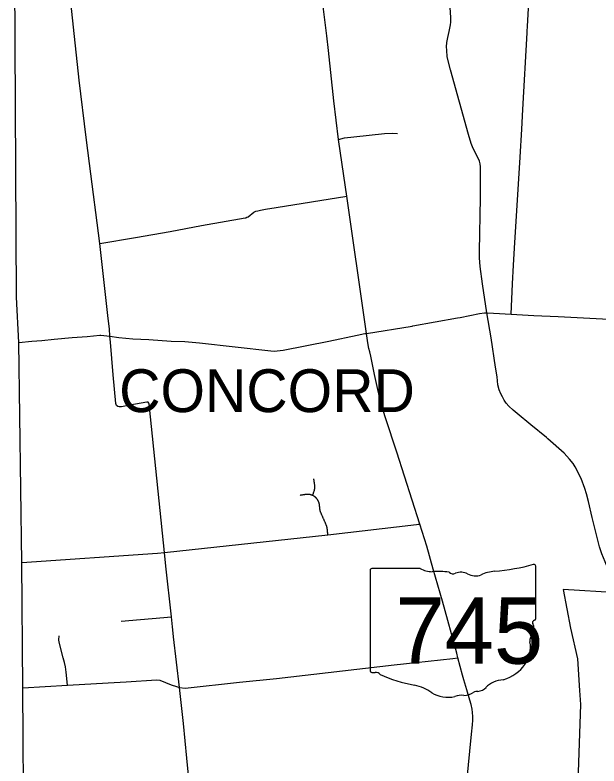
# Model space of a CAD drawing. Extents: x 1729596 to 1925846, y 659247 to 911751.
# Drawn here: x 1780895 to 1793175, y 791458 to 807237 of the extents above; entities that cross this region are included whole.
import ezdxf

# ---------------------------------------------------------------- set-up
doc = ezdxf.new("R2010")
doc.units = 0
for name, color, linetype in [('GM_X_County', 7, 'Continuous'), ('GM_X_County_Road', 7, 'Continuous'), ('GM_X_State_Route', 7, 'Continuous'), ('GM_X_State_Shield', 7, 'Continuous'), ('GM_X_Township', 7, 'Continuous'), ('GM_X_Township_Road', 7, 'Continuous'), ('GM_X_Township_Text', 7, 'Continuous')]:
    doc.layers.add(name, color=color, linetype=linetype)

msp = doc.modelspace()

# ---------------------------------------------------------------- linework, layer by layer
at = {"layer": 'GM_X_County'}
msp.add_lwpolyline([(1781083, 789921), (1781062, 793102), (1781040, 795733), (1780979, 800357), (1780927, 801312), (1780895, 808002)], dxfattribs=at)
at = {"layer": 'GM_X_County_Road'}
for points in [[(1782890, 800490), (1782881, 800644), (1782856, 800863), (1782676, 802437), (1782464, 804119), (1782395, 804661), (1782246, 805871), (1782006, 808105), (1781669, 811078), (1781659, 811109), (1781650, 811131), (1781636, 811151)], [(1791328, 800949), (1791359, 801588), (1791381, 801980), (1791400, 802336), (1791517, 804248), (1791555, 804839), (1791576, 805255), (1791663, 806861), (1791666, 806898), (1791673, 806996), (1791713, 807764)], [(1790259, 800884), (1790662, 800965), (1790767, 800980), (1790816, 800981)], [(1790816, 800981), (1790957, 800973), (1791328, 800949), (1791805, 800926), (1792317, 800900), (1794586, 800781), (1795455, 800738), (1796520, 800687)], [(1789248, 800701), (1789260, 800704), (1790202, 800872), (1790259, 800884)], [(1788284, 800545), (1789248, 800701)], [(1780979, 800357), (1781251, 800385), (1781456, 800401), (1781721, 800423), (1782095, 800460), (1782415, 800484), (1782676, 800509), (1782703, 800508), (1782890, 800490), (1783080, 800464), (1783370, 800430), (1783710, 800417), (1784177, 800386), (1784465, 800376), (1784774, 800347), (1786277, 800180), (1786348, 800171), (1786537, 800193), (1787491, 800386), (1788093, 800511), (1788252, 800542), (1788284, 800545)], [(1784231, 794169), (1784213, 794320), (1784208, 794381), (1784184, 794592), (1784065, 795658), (1784036, 795945), (1783745, 798796), (1783719, 799058), (1783710, 799082), (1783697, 799100), (1783664, 799103), (1783307, 799040), (1783135, 799003), (1783086, 799003), (1783057, 799012), (1783029, 799032), (1783012, 799071), (1782957, 799680), (1782900, 800360), (1782890, 800490)], [(1784354, 793107), (1784231, 794169)]]:
    msp.add_lwpolyline(points, dxfattribs=at)
at = {"layer": 'GM_X_State_Route'}
for points in [[(1790208, 793730), (1790185, 793831), (1789883, 794924), (1789691, 795593), (1789552, 796074), (1789406, 796539), (1788925, 798054), (1788685, 798770), (1788593, 799061), (1788574, 799137), (1788559, 799211), (1788513, 799432), (1788454, 799683), (1788376, 800070), (1788357, 800160), (1788339, 800233), (1788316, 800352), (1788284, 800545), (1788263, 800693), (1787872, 803431), (1787846, 803622), (1787700, 804624), (1787601, 805437), (1787484, 806491), (1787451, 806800), (1787357, 807594)], [(1790677, 804093), (1790675, 804108), (1790660, 804164), (1790640, 804215), (1790609, 804281), (1790568, 804355), (1790526, 804429), (1790485, 804541), (1790432, 804726), (1790051, 806083), (1789985, 806362), (1789973, 806499), (1789971, 806567), (1789977, 806663), (1789996, 806768), (1790026, 806892), (1790053, 807030), (1790058, 807087), (1790058, 807184), (1790033, 807604)], [(1790684, 803416), (1790687, 803933), (1790683, 804011), (1790681, 804061), (1790677, 804093)], [(1790816, 800981), (1790725, 801587), (1790674, 801951), (1790662, 802137), (1790662, 802272), (1790684, 803396), (1790684, 803416)], [(1792099, 798333), (1792069, 798359), (1791739, 798628), (1791453, 798865), (1791371, 798933), (1791282, 799017), (1791224, 799083), (1791180, 799145), (1791143, 799214), (1791110, 799281), (1791078, 799363), (1791051, 799466), (1791032, 799632), (1791000, 799840), (1790910, 800451), (1790816, 800981)], [(1793626, 794462), (1793626, 794462), (1793641, 794594), (1793644, 794648), (1793641, 794771), (1793623, 794897), (1793613, 794945), (1793580, 795059), (1793566, 795094), (1793498, 795270), (1793303, 795745), (1793237, 795913), (1793188, 796062), (1793091, 796453), (1793034, 796681), (1792957, 797013), (1792916, 797174), (1792881, 797288), (1792802, 797495), (1792672, 797742), (1792629, 797811), (1792556, 797903), (1792444, 798033), (1792099, 798333)], [(1790307, 793367), (1790208, 793730)], [(1790432, 790335), (1790390, 790706), (1790390, 790920), (1790399, 791128), (1790496, 792123), (1790514, 792320), (1790520, 792424), (1790521, 792501), (1790516, 792584), (1790507, 792652), (1790487, 792748), (1790462, 792838), (1790399, 793056), (1790334, 793268), (1790307, 793367)]]:
    msp.add_lwpolyline(points, dxfattribs=at)
at = {"layer": 'GM_X_State_Shield'}
for p, q in [((1789418, 795607), (1788399, 795607)), ((1789418, 795607), (1788399, 795607)), ((1791845, 794554), (1791845, 795660)), ((1791845, 794554), (1791845, 795660)), ((1788365, 795571), (1788365, 793458)), ((1788365, 795571), (1788365, 793458)), ((1791845, 794555), (1791845, 794554)), ((1791845, 794555), (1791845, 794554))]:
    msp.add_line(p, q, dxfattribs=at)
for centre, major_axis, start_param, end_param in [((1788404, 795576), (40.3, 0), 1.712693, 3.28349), ((1788404, 795576), (40.3, 0), 1.712693, 3.28349), ((1789661, 795853), (391, 0), 4.042523, 4.731795), ((1789661, 795853), (391, 0), 4.042523, 4.731795), ((1790605, 798489), (3691, 0), 4.814394, 5.042369), ((1790605, 798489), (3691, 0), 4.814394, 5.042369), ((1791806, 795664), (38.7, 0), 6.141152, 7.989035), ((1791806, 795664), (38.7, 0), 6.141152, 7.989035), ((1789791, 794421), (1404, 0), 1.404758, 1.657858), ((1789791, 794421), (1404, 0), 1.404758, 1.657858), ((1790109, 795587), (113, 0), 3.836095, 5.185415), ((1790109, 795587), (113, 0), 3.836095, 5.185415), ((1790275, 795342), (235, 0), 0.950623, 2.079405), ((1790275, 795342), (235, 0), 0.950623, 2.079405), ((1790578, 795677), (282, 0), 4.081561, 5.145723), ((1790578, 795677), (282, 0), 4.081561, 5.145723), ((1791076, 794962), (743, 0), 1.699011, 2.107814), ((1791076, 794962), (743, 0), 1.699011, 2.107814), ((1791836, 794473), (60, 0), 1.883978, 3.671073), ((1791836, 794473), (60, 0), 1.883978, 3.671073), ((1791804, 794550), (41.5, 0), 5.05454, 6.418171), ((1791804, 794550), (41.5, 0), 5.05454, 6.418171), ((1791455, 794333), (360, 0), 5.934695, 6.695948), ((1791455, 794333), (360, 0), 5.934695, 6.695948), ((1791984, 794092), (262, 0), 2.387724, 3.262537), ((1791984, 794092), (262, 0), 2.387724, 3.262537), ((1790812, 793951), (923, 0), 5.101752, 6.440018), ((1790812, 793951), (923, 0), 5.101752, 6.440018), ((1788405, 793453), (40.7, 0), 3.00124, 4.508301), ((1788405, 793453), (40.7, 0), 3.00124, 4.508301), ((1788411, 793669), (310, 0), 4.665946, 4.897461), ((1788411, 793669), (310, 0), 4.665946, 4.897461), ((1788475, 793336), (112, 0), 0.519207, 1.627899), ((1788475, 793336), (112, 0), 0.519207, 1.627899), ((1789888, 795235), (2665, 0), 4.195997, 4.488961), ((1789888, 795235), (2665, 0), 4.195997, 4.488961), ((1791201, 792864), (506, 0), 1.647645, 2.488434), ((1791201, 792864), (506, 0), 1.647645, 2.488434), ((1789093, 792508), (834, 0), 0.823519, 1.323587), ((1789093, 792508), (834, 0), 0.823519, 1.323587), ((1790561, 793253), (298, 0), 4.937069, 5.64225), ((1790561, 793253), (298, 0), 4.937069, 5.64225), ((1789995, 793325), (529, 0), 4.026481, 4.996735), ((1789995, 793325), (529, 0), 4.026481, 4.996735), ((1790301, 792595), (435, 0), 1.495662, 1.94098), ((1790301, 792595), (435, 0), 1.495662, 1.94098), ((1790339, 793167), (282, 0), 4.691044, 5.507374), ((1790339, 793167), (282, 0), 4.691044, 5.507374), ((1790595, 792962), (79.4, 0), 1.147584, 2.315152), ((1790595, 792962), (79.4, 0), 1.147584, 2.315152)]:
    msp.add_ellipse(centre, major_axis=major_axis, ratio=0.8, start_param=start_param, end_param=end_param, dxfattribs=at)
at = {"layer": 'GM_X_Township'}
msp.add_lwpolyline([(1793566, 795094), (1792419, 795165), (1792576, 794356), (1792720, 793710), (1792764, 793045), (1792783, 792753), (1792702, 790313), (1792702, 789519), (1792745, 788755), (1792845, 788222), (1793028, 787628), (1793570, 786064)], dxfattribs=at)
at = {"layer": 'GM_X_Township_Road'}
for points in [[(1787700, 804624), (1787823, 804655), (1788019, 804676), (1788666, 804747), (1788824, 804753), (1788939, 804749)], [(1782676, 802437), (1783430, 802559), (1784155, 802688), (1784818, 802812), (1785735, 802974), (1785747, 802978), (1785772, 802987), (1785797, 802999), (1785838, 803032), (1785874, 803062), (1785916, 803092), (1785959, 803113), (1786003, 803125), (1786060, 803139), (1786163, 803159), (1786385, 803195), (1787872, 803431)], [(1787154, 797141), (1787157, 797150), (1787160, 797159), (1787163, 797168), (1787166, 797177), (1787169, 797185), (1787172, 797194), (1787175, 797203), (1787178, 797212), (1787181, 797221), (1787184, 797230), (1787187, 797238), (1787189, 797242), (1787190, 797247), (1787191, 797251), (1787192, 797255), (1787194, 797259), (1787195, 797263), (1787196, 797267), (1787196, 797272), (1787197, 797276), (1787198, 797280), (1787199, 797284), (1787199, 797288), (1787200, 797293), (1787200, 797297), (1787200, 797301), (1787201, 797306), (1787201, 797310), (1787201, 797314), (1787201, 797319), (1787201, 797323), (1787201, 797327), (1787201, 797331), (1787201, 797336), (1787200, 797340), (1787200, 797344), (1787199, 797349), (1787199, 797353), (1787198, 797357), (1787197, 797366), (1787196, 797376), (1787194, 797385), (1787193, 797395), (1787191, 797404), (1787190, 797413), (1787188, 797423), (1787187, 797432), (1787186, 797442), (1787184, 797451), (1787183, 797460), (1787181, 797470), (1787180, 797479), (1787178, 797489)], [(1787475, 796318), (1787474, 796328), (1787473, 796338), (1787472, 796348), (1787471, 796358), (1787469, 796367), (1787468, 796377), (1787467, 796387), (1787466, 796397), (1787465, 796406), (1787464, 796416), (1787463, 796426), (1787462, 796436), (1787461, 796445), (1787460, 796450), (1787460, 796454), (1787459, 796458), (1787458, 796462), (1787458, 796466), (1787457, 796470), (1787456, 796474), (1787455, 796479), (1787454, 796483), (1787453, 796487), (1787452, 796491), (1787450, 796495), (1787449, 796499), (1787448, 796503), (1787446, 796507), (1787445, 796511), (1787443, 796514), (1787441, 796518), (1787437, 796527), (1787433, 796536), (1787429, 796545), (1787425, 796555), (1787421, 796564), (1787418, 796573), (1787414, 796582), (1787410, 796591), (1787406, 796600), (1787402, 796609), (1787398, 796618), (1787394, 796627), (1787390, 796636), (1787386, 796645), (1787382, 796654), (1787378, 796663), (1787374, 796672), (1787370, 796681), (1787366, 796690), (1787362, 796699), (1787358, 796708), (1787354, 796717), (1787350, 796726), (1787346, 796735), (1787342, 796744), (1787338, 796753), (1787334, 796762), (1787330, 796772), (1787326, 796781), (1787325, 796784), (1787323, 796788), (1787322, 796792), (1787320, 796796), (1787319, 796800), (1787317, 796804), (1787316, 796808), (1787315, 796812), (1787314, 796816), (1787313, 796820), (1787312, 796824), (1787311, 796828), (1787310, 796832), (1787309, 796836), (1787309, 796840), (1787308, 796844), (1787307, 796848), (1787307, 796852), (1787306, 796857), (1787306, 796866), (1787305, 796875), (1787304, 796884), (1787303, 796893), (1787302, 796902), (1787301, 796911), (1787300, 796920), (1787299, 796930), (1787298, 796939), (1787298, 796943), (1787297, 796947), (1787297, 796952), (1787296, 796956), (1787295, 796960), (1787294, 796964), (1787294, 796969), (1787293, 796973), (1787292, 796977), (1787290, 796981), (1787289, 796986), (1787288, 796990), (1787287, 796994), (1787285, 796998), (1787284, 797002), (1787282, 797006), (1787280, 797010), (1787279, 797014), (1787277, 797018), (1787275, 797022), (1787273, 797026), (1787271, 797030), (1787269, 797034), (1787267, 797037), (1787266, 797039), (1787265, 797041), (1787263, 797045), (1787260, 797049), (1787258, 797052), (1787256, 797056), (1787253, 797059), (1787251, 797063), (1787248, 797066), (1787245, 797070), (1787243, 797073), (1787240, 797076), (1787237, 797080), (1787234, 797083), (1787231, 797086), (1787228, 797089), (1787225, 797092), (1787222, 797095), (1787219, 797098), (1787216, 797101), (1787212, 797104), (1787209, 797107), (1787206, 797110), (1787202, 797112), (1787199, 797115), (1787195, 797117), (1787192, 797120), (1787188, 797122), (1787184, 797125), (1787181, 797127), (1787177, 797129), (1787173, 797132), (1787169, 797134), (1787166, 797136), (1787162, 797138), (1787158, 797140), (1787154, 797141), (1787150, 797143), (1787146, 797145), (1787142, 797147), (1787138, 797148), (1787134, 797150), (1787130, 797151), (1787126, 797152), (1787122, 797154), (1787118, 797155), (1787114, 797156), (1787109, 797157), (1787105, 797158), (1787101, 797159), (1787097, 797160), (1787093, 797161), (1787088, 797161), (1787084, 797162), (1787080, 797162), (1787076, 797163), (1787071, 797163), (1787067, 797164), (1787063, 797164), (1787059, 797164), (1787054, 797164), (1787050, 797164), (1787046, 797164), (1787041, 797164), (1787037, 797164), (1787033, 797164), (1787029, 797163), (1787024, 797163), (1787020, 797163), (1787016, 797162), (1787012, 797161), (1787002, 797160), (1786993, 797159), (1786984, 797157), (1786974, 797156), (1786965, 797154), (1786956, 797153), (1786946, 797152), (1786937, 797150), (1786928, 797149), (1786918, 797147), (1786909, 797146), (1786900, 797145), (1786890, 797143)], [(1781040, 795733), (1783893, 795933), (1784036, 795945), (1787475, 796318), (1789335, 796532), (1789379, 796538), (1789406, 796539)], [(1783128, 794500), (1784184, 794592)], [(1781996, 793155), (1781969, 793427), (1781956, 793540), (1781937, 793633), (1781911, 793728), (1781821, 794057), (1781818, 794111), (1781821, 794191)], [(1784293, 793126), (1784354, 793107), (1784475, 793093), (1785619, 793219), (1786396, 793298), (1788869, 793586), (1789322, 793635), (1790104, 793716), (1790208, 793730)], [(1781062, 793102), (1781996, 793155), (1782851, 793208), (1783230, 793226), (1783871, 793267), (1783940, 793261), (1784180, 793162), (1784293, 793126)], [(1784638, 790333), (1784509, 791619), (1784435, 792353), (1784354, 793107)]]:
    msp.add_lwpolyline(points, dxfattribs=at)

# ---------------------------------------------------------------- texts
at = {"layer": 'GM_X_State_Shield'}
msp.add_text('745', height=1392.2, dxfattribs=at).set_placement((1788896, 793607))
msp.add_text('745', height=1392.2, dxfattribs=at).set_placement((1788896, 793607))
at = {"layer": 'GM_X_Township_Text'}
msp.add_text('CONCORD', height=900, rotation=0, dxfattribs=at).set_placement((1783085, 798893))

doc.saveas('drawing.dxf')
